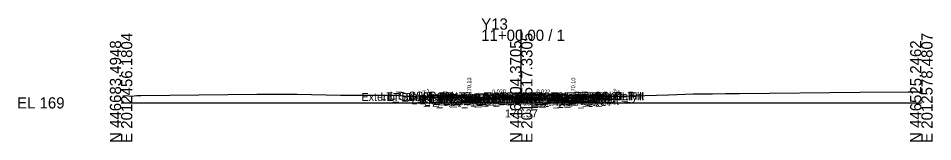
# Model space of a CAD drawing. Extents: x -26 to 1403, y -10 to 4517.
# Drawn here: x -25.7 to 202.8, y 1990.3 to 2021.1 of the extents above; entities that cross this region are included whole.
import ezdxf

# ---------------------------------------------------------------- set-up
doc = ezdxf.new("R2010")
doc.units = 0
for name, color, linetype in [('Default', 7, 'Continuous'), ('Exist CMT Pavement', 7, 'Continuous'), ('Exist Cross Section Cell', 7, 'Continuous'), ('Exist XS Center Line Elevation Label', 7, 'Continuous'), ('Exist XS Ground Line', 7, 'Continuous'), ('Prop CMT Conc Surface', 7, 'Continuous'), ('Prop CMT Concrete Structures', 7, 'Continuous'), ('Prop CMT Pvmt Course 1', 7, 'Continuous'), ('Prop CMT Pvmt Course 1 CG', 7, 'Continuous'), ('Prop CMT Pvmt Course 1 Wedge', 7, 'Continuous'), ('Prop CMT Pvmt Course 2', 7, 'Continuous'), ('Prop CMT Pvmt Course 3', 7, 'Continuous'), ('Prop CMT Pvmt Surface', 7, 'Continuous'), ('Prop CMT Pvmt Wedge Surface 1', 7, 'Continuous'), ('Prop CMT Pvmt Wedge Surface 2', 7, 'Continuous'), ('Prop CMT Pvmt Wedge Surface 3', 7, 'Continuous'), ('Prop CMT Slope Grass', 7, 'Continuous'), ('Prop CMT Subgrade Earthwork', 7, 'Continuous'), ('Prop XS Earthwork Shape', 7, 'Continuous'), ('Prop XS Hydro Elevations', 7, 'Continuous'), ('Prop XS SE Text', 7, 'Continuous'), ('Prop XS Side Slope Text', 7, 'Continuous'), ('Scratch_Level_0', 7, 'Continuous')]:
    doc.layers.add(name, color=color, linetype=linetype)

msp = doc.modelspace()

# ---------------------------------------------------------------- linework, layer by layer
at = {"layer": 'Exist CMT Pavement'}
for points in [[(100, 2001.37), (99.99, 2001.37), (97.65, 2001.32), (90.01, 2001.08)], [(100, 2001.37), (102.34, 2001.31), (110, 2001.08)]]:
    msp.add_lwpolyline(points, dxfattribs=at)
at = {"layer": 'Exist Cross Section Cell'}
for p, q in [((100, 2000), (100, 2018.29)), ((0, 2000), (100, 2000)), ((100, 2000), (200, 2000))]:
    msp.add_line(p, q, dxfattribs=at)
at = {"layer": 'Exist XS Ground Line'}
msp.add_lwpolyline([(0.41, 2001.78), (1.3, 2001.81), (2.5, 2001.67), (3.9, 2001.81), (4.94, 2001.84), (33.94, 2002.17), (35.01, 2002.17), (44.04, 2002.17), (54.84, 2001.9), (56.3, 2001.92), (67.65, 2001.9), (68.94, 2001.89), (69.32, 2001.88), (76.23, 2001.45), (80.13, 2001.39), (87.47, 2001.33), (89.2, 2001.05), (99.99, 2001.37), (111.39, 2001.04), (113, 2001.28), (116.78, 2001.4), (121.98, 2001.59), (136.79, 2002.02), (143, 2002.23), (147.83, 2002.26), (151.1, 2002.36), (154.53, 2002.35), (184.59, 2002.64), (196.68, 2002.74), (197.44, 2002.77), (200, 2002.78)], dxfattribs=at)
at = {"layer": 'Prop CMT Conc Surface'}
for points in [[(87, 2001.13), (87, 2001.63), (86.5, 2001.63)], [(89, 2001.25), (87, 2001.13)], [(111, 2001.22), (113, 2001.1)], [(113, 2001.1), (113, 2001.6), (113.5, 2001.6)]]:
    msp.add_lwpolyline(points, dxfattribs=at)
at = {"layer": 'Prop CMT Concrete Structures'}
for points in [[(89, 2001.25), (87, 2001.13), (87, 2001.63), (86.5, 2001.63)], [(86.5, 2001.63), (86.5, 2000.61), (89, 2000.66)], [(89, 2000.66), (89, 2001.25)], [(111, 2001.22), (113, 2001.1), (113, 2001.6), (113.5, 2001.6)], [(113.5, 2001.6), (113.5, 2000.58), (111, 2000.64)], [(111, 2000.64), (111, 2001.22)]]:
    msp.add_lwpolyline(points, dxfattribs=at)
at = {"layer": 'Prop CMT Pvmt Course 1'}
for points in [[(100, 2001.47), (89, 2001.25)], [(89, 2001.25), (89, 2001)], [(89, 2001), (90, 2001.02)], [(90, 2001.14), (100, 2001.34)], [(90, 2001.02), (90, 2001.14)], [(100, 2001.22), (100, 2001.47)], [(100, 2001.47), (111, 2001.22)], [(100, 2001.22), (100, 2001.47)], [(100, 2001.34), (100, 2001.22), (100, 2001.22)], [(110, 2001.12), (100, 2001.34)], [(100, 2001.34), (100, 2001.22), (100, 2001.22)], [(110, 2000.99), (110, 2001.12)], [(111, 2000.97), (110, 2000.99)], [(111, 2001.22), (111, 2000.97)]]:
    msp.add_lwpolyline(points, dxfattribs=at)
at = {"layer": 'Prop CMT Pvmt Course 1 CG'}
for points in [[(89, 2000.66), (86, 2000.6), (85.66, 2000.26)], [(85.66, 2000.26), (89, 2000.33)], [(89, 2000.33), (89, 2000.66)], [(111, 2000.64), (114, 2000.57), (114.34, 2000.23)], [(111, 2000.3), (111, 2000.64)], [(114.34, 2000.23), (111, 2000.3)]]:
    msp.add_lwpolyline(points, dxfattribs=at)
at = {"layer": 'Prop CMT Pvmt Course 1 Wedge'}
for points in [[(90, 2001.14), (95.67, 2001.26)], [(95.67, 2001.26), (90, 2001.08)], [(90, 2001.08), (90, 2001.14)], [(110, 2001.08), (105.13, 2001.23)], [(105.13, 2001.23), (110, 2001.12)], [(110, 2001.12), (110, 2001.08)]]:
    msp.add_lwpolyline(points, dxfattribs=at)
at = {"layer": 'Prop CMT Pvmt Course 2'}
for points in [[(90, 2001.02), (89, 2001)], [(89, 2001), (89, 2000.66)], [(89, 2000.66), (90, 2000.68)], [(90, 2000.68), (90, 2001.02)], [(110, 2000.66), (110, 2000.99)], [(110, 2000.99), (111, 2000.97)], [(111, 2000.64), (110, 2000.66)], [(111, 2000.97), (111, 2000.64)]]:
    msp.add_lwpolyline(points, dxfattribs=at)
at = {"layer": 'Prop CMT Pvmt Course 3'}
for points in [[(90, 2000.68), (89, 2000.66)], [(89, 2000.66), (89, 2000.33)], [(89, 2000.33), (90, 2000.35)], [(90, 2000.35), (90, 2000.68)], [(110, 2000.66), (111, 2000.64)], [(110, 2000.33), (110, 2000.66)], [(111, 2000.3), (110, 2000.33)], [(111, 2000.64), (111, 2000.3)]]:
    msp.add_lwpolyline(points, dxfattribs=at)
at = {"layer": 'Prop CMT Pvmt Surface'}
for points in [[(100, 2001.47), (89, 2001.25)], [(100, 2001.47), (111, 2001.22)]]:
    msp.add_lwpolyline(points, dxfattribs=at)
at = {"layer": 'Prop CMT Pvmt Wedge Surface 1'}
for points in [[(89, 2001), (89, 2001.25)], [(90, 2001.02), (89, 2001)], [(100, 2001.34), (90, 2001.14)], [(90, 2001.14), (90, 2001.02)], [(100, 2001.34), (110, 2001.12)], [(110, 2001.12), (110, 2000.99)], [(110, 2000.99), (111, 2000.97)], [(111, 2000.97), (111, 2001.22)]]:
    msp.add_lwpolyline(points, dxfattribs=at)
at = {"layer": 'Prop CMT Pvmt Wedge Surface 2'}
for points in [[(89, 2001), (89, 2001.25)], [(100, 2001.22), (89, 2001)], [(100, 2001.22), (111, 2000.97)], [(111, 2000.97), (111, 2001.22)]]:
    msp.add_lwpolyline(points, dxfattribs=at)
at = {"layer": 'Prop CMT Pvmt Wedge Surface 3'}
for points in [[(89, 2000.66), (89, 2001.25)], [(100, 2000.88), (89, 2000.66)], [(100, 2000.88), (111, 2000.64)], [(111, 2000.64), (111, 2001.22)]]:
    msp.add_lwpolyline(points, dxfattribs=at)
at = {"layer": 'Prop CMT Slope Grass'}
for points in [[(86.5, 2001.63), (77, 2001.82), (75.96, 2001.47)], [(113.5, 2001.6), (123, 2001.79), (123.45, 2001.64)]]:
    msp.add_lwpolyline(points, dxfattribs=at)
at = {"layer": 'Prop CMT Subgrade Earthwork'}
for points in [[(89, 2000.33), (85.66, 2000.26), (84.25, 2001.67)], [(90, 2000.35), (89, 2000.33)], [(90, 2000.35), (90.01, 2001.08)], [(110, 2000.33), (110, 2001.08)], [(110, 2000.33), (111, 2000.3)], [(111, 2000.3), (114.34, 2000.23), (115.75, 2001.64)]]:
    msp.add_lwpolyline(points, dxfattribs=at)
at = {"layer": 'Prop XS Earthwork Shape'}
for points in [[(77, 2001.82), (75.96, 2001.47), (76.23, 2001.45), (80.13, 2001.39), (84.57, 2001.35), (84.25, 2001.67)], [(90, 2000.35), (90.01, 2001.08), (89.2, 2001.05), (89, 2001.09), (89, 2000.66), (86.5, 2000.61), (86.5, 2001.34), (84.57, 2001.35), (85.66, 2000.26), (89, 2000.33)], [(88.26, 2001.2), (87, 2001.13), (87, 2001.33), (86.5, 2001.34), (86.5, 2000.61), (89, 2000.66), (89, 2001.09)], [(88.26, 2001.2), (87, 2001.13), (87, 2001.33), (87.47, 2001.33)], [(90.01, 2001.08), (100, 2001.37), (97.65, 2001.32)], [(100, 2001.37), (102.34, 2001.31), (110, 2001.08)], [(110, 2000.33), (111, 2000.3), (114.34, 2000.23), (115.47, 2001.36), (113.5, 2001.29), (113.5, 2000.58), (111, 2000.64), (111, 2001.05), (110, 2001.08)], [(111, 2000.64), (111, 2001.05), (111.39, 2001.04), (112.13, 2001.15), (113, 2001.1), (113, 2001.28), (113.5, 2001.29), (113.5, 2000.58)], [(113, 2001.1), (113, 2001.28), (112.13, 2001.15)], [(123, 2001.79), (123.45, 2001.64), (121.98, 2001.59), (116.78, 2001.4), (115.47, 2001.36), (115.75, 2001.64)]]:
    msp.add_lwpolyline(points, close=True, dxfattribs=at)

# ---------------------------------------------------------------- texts
at = {"layer": 'Default'}
msp.add_text('-', height=0.0001, dxfattribs=at).set_placement((0, 2000))
at = {"layer": 'Exist Cross Section Cell'}
for s, p in [('Y13', (90, 2018.29)), ('11+00.00 / 1', (90, 2015.49)), ('EL 169', (-26, 1998.6))]:
    msp.add_text(s, height=2.8, dxfattribs=at).set_placement(p)
for s, p in [('E 2012456.1804', (2.8, 1990)), ('E 2012517.3305', (102.8, 1990)), ('E 2012578.4807', (202.8, 1990)), ('N 446683.4948', (0, 1990)), ('N 446604.3705', (100, 1990)), ('N 446525.2462', (200, 1990))]:
    msp.add_text(s, height=2.8, rotation=90, dxfattribs=at).set_placement(p)
at = {"layer": 'Exist XS Center Line Elevation Label'}
msp.add_text('170.37', height=2, dxfattribs=at).set_placement((95.94, 1996.37))
at = {"layer": 'Prop XS Hydro Elevations'}
for s, p in [('170.13', (87.5, 2002.13)), ('170.10', (113.5, 2002.1))]:
    msp.add_text(s, height=1, rotation=90, dxfattribs=at).set_placement(p)
at = {"layer": 'Prop XS SE Text'}
for s, rotation, p in [('0.020', 1.1458, (92.73, 2002.32)), ('0.022', 358.7111, (103.81, 2002.38))]:
    msp.add_text(s, height=1, rotation=rotation, dxfattribs=at).set_placement(p)
at = {"layer": 'Prop XS Side Slope Text'}
for rotation, p in [(18.4332, (75.49, 2002.11)), (341.5668, (122.71, 2002.67))]:
    msp.add_text('3:1', height=1, rotation=rotation, dxfattribs=at).set_placement(p)
at = {"layer": 'Scratch_Level_0'}
for s, p in [('Exterior Boundary', (60.1, 2000.47)), ('LT_Sub_Trench_Out_DLT', (64.82, 2000.67)), ('LT_Slope_Fill', (66.48, 2000.47)), ('LT_CSLP_Pnt', (67.17, 2000.82)), ('LT_CG_Top_Face', (74.26, 2000.63)), ('LT_CG_Top_BOC', (74.78, 2000.63)), ('LT_PV_Sub_Tie_Out', (74.96, 2000.08)), ('LT_CG_Top_Gut', (75.24, 2000.13)), ('LT_PV_OEEOP_EG', (77.54, 2000.08)), ('LT_PV2_OEOT', (79.17, 2000)), ('LT_PV2_OEEOP', (79.31, 2000.02)), ('LT_PV1_OEOT', (79.74, 2000.25)), ('LT_PV1_OEEOP', (79.87, 2000.14)), ('RT_PV_IEEOP_EG', (88.14, 2000.37)), ('LT_PV_IEEOP_EG', (88.19, 2000.37)), ('RT_PV2_IEEOP', (89.91, 2000.22)), ('LT_PV2_IEEOP', (89.95, 2000.22)), ('RT_PV1_IEEOP', (90.47, 2000.34)), ('LT_PV1_IEEOP', (90.52, 2000.34)), ('PV2_PGL', (93.91, 2000.22)), ('PV1_PGL', (94.47, 2000.47)), ('RT_PV_Sub_Tie_Out', (94.88, 2000.08)), ('RT_Sub_Trench_Out_DLT', (96.27, 2000.64)), ('RT_PV_OEEOP_EG', (97.5, 2000.08)), ('RT_PV2_OEEOP', (99.26, 1999.99)), ('RT_PV1_OEEOP', (99.83, 2000.12)), ('RT_CG_Top_Face', (100.21, 2000.6)), ('RT_PV2_OEOT', (101.13, 1999.97)), ('RT_CG_Top_Gut', (101.19, 2000.1)), ('RT_PV1_OEOT', (101.69, 2000.22)), ('RT_CG_Top_BOC', (101.74, 2000.6)), ('Exterior Boundary', (107.59, 2000.64)), ('RT_CSLP_Pnt', (113.13, 2000.79)), ('RT_Slope_Fill', (113.92, 2000.64)), ('LT_CG1_Shelf_Out', (72.55, 1999.6)), ('LT_CG_Bot_BOC', (74.81, 1999.61)), ('LT_Sub_OEOP', (75.77, 1999.26)), ('LT_CG_Bot_IE', (78.91, 1999.66)), ('LT_Sub_OEOT', (79.08, 1999.33)), ('LT_PV3_OEOT', (79.17, 1999.66)), ('LT_Sub_OEEOP', (79.21, 1999.35)), ('LT_PV3_OEEOP', (79.31, 1999.68)), ('RT_PV3_IEEOP', (89.91, 1999.88)), ('LT_PV3_IEEOP', (89.95, 1999.88)), ('RT_Sub_OEEOP', (99.17, 1999.33)), ('RT_PV3_OEEOP', (99.26, 1999.66)), ('RT_CG1_Shelf_Out', (100.5, 1999.57)), ('RT_CG_Bot_IE', (100.87, 1999.64)), ('RT_Sub_OEOT', (101.03, 1999.3)), ('RT_PV3_OEOT', (101.13, 1999.64)), ('RT_CG_Bot_BOC', (101.77, 1999.58)), ('RT_Sub_OEOP', (104.4, 1999.23))]:
    msp.add_text(s, height=2, dxfattribs=at).set_placement(p)

doc.saveas('drawing.dxf')
